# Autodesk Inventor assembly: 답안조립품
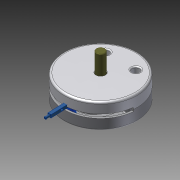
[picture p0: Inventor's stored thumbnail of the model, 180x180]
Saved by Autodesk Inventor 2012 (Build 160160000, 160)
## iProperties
Created: 2015-04
Part Number: 답안조립품
Document SubType Name: Assembly
Designer: Owner
Author: Owner
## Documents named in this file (10)
- C:\Documents and Settings\Owner\바탕 화면\450405V1007\답안조립품.iam
- C:\Documents and Settings\Owner\바탕 화면\450405V1007\1 본체.ipt
- C:\Documents and Settings\Owner\바탕 화면\450405V1007\베어링62_22.ipt
- C:\Documents and Settings\Owner\바탕 화면\450405V1007\덮개.ipt
- C:\Documents and Settings\Owner\바탕 화면\450405V1007\축.ipt
- C:\Documents and Settings\Owner\바탕 화면\450405V1007\멈춤링.ipt
- C:\Documents and Settings\Owner\바탕 화면\450405V1007\평행핀.ipt
- C:\Documents and Settings\Owner\바탕 화면\450405V1007\슬라이더2.ipt
- C:\Documents and Settings\Owner\바탕 화면\450405V1007\슬라이더.ipt
- C:\Documents and Settings\Owner\바탕 화면\450405V1007\M 10 x 35.ipt
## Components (3 placed, 2 different names)
1. 1 본체:1
2. M 10 x 35:1
3. M 10 x 35:2
